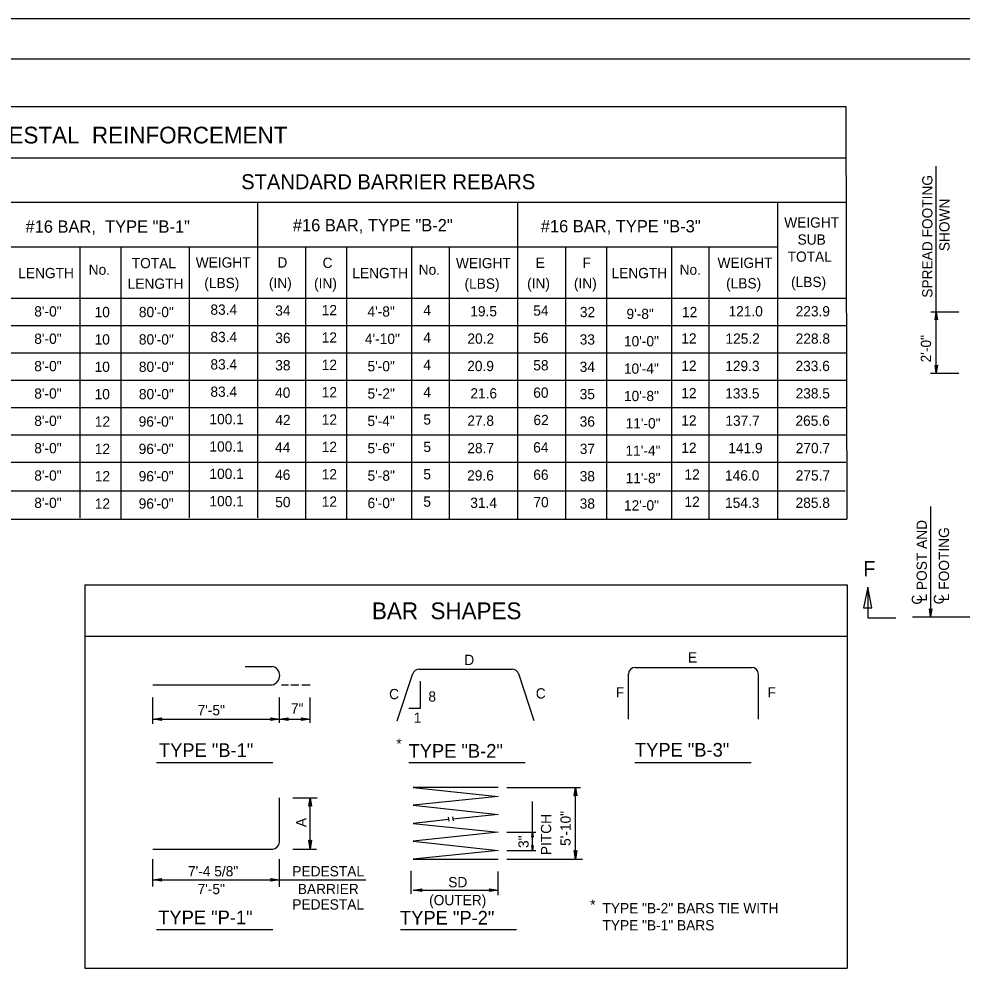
# Model space of a CAD drawing. Extents: x -3 to 26050223, y 0 to 12035012.
# Drawn here: x 21.31 to 44.29, y 20.2 to 43.33 of the extents above; entities that cross this region are included whole.
import ezdxf

# ---------------------------------------------------------------- set-up
doc = ezdxf.new("R2010")
doc.units = 0
for name, color, linetype in [('1', 7, 'Continuous'), ('2', 7, 'Continuous'), ('39', 7, 'Continuous')]:
    doc.layers.add(name, color=color, linetype=linetype)

msp = doc.modelspace()

# ---------------------------------------------------------------- linework, layer by layer
at = {"layer": '1'}
for p, q in [((68.892, 43.325), (0, 43.325)), ((68.183, 42.342), (3.6, 42.342))]:
    msp.add_line(p, q, dxfattribs=at)
at = {"layer": '2'}
for p, q in [((24.658, 25.208), (27.492, 25.208)), ((30.808, 25.208), (33.642, 25.208)), ((36.317, 25.208), (39.15, 25.208)), ((24.658, 21.142), (27.492, 21.142)), ((30.6, 21.142), (33.433, 21.142))]:
    msp.add_line(p, q, dxfattribs=at)
msp.add_arc((27.429, 27.325), 0.23, 281.6527, 78.3473, dxfattribs=at)
at = {"layer": '39'}
for p, q in [((4.871, 41.192), (41.454, 41.192)), ((41.454, 41.192), (41.482, 31.137)), ((4.871, 39.942), (41.454, 39.942)), ((43.658, 34.692), (43.658, 39.742)), ((9.121, 38.859), (41.454, 38.859)), ((27.121, 38.859), (27.121, 31.173)), ((33.454, 38.859), (33.454, 31.14)), ((39.788, 38.859), (39.788, 31.124)), ((9.121, 37.776), (39.788, 37.776)), ((22.788, 37.776), (22.788, 31.173)), ((23.788, 37.776), (23.788, 31.124)), ((25.454, 37.776), (25.454, 31.173)), ((28.288, 37.776), (28.288, 31.156)), ((29.288, 37.776), (29.288, 31.14)), ((30.871, 37.776), (30.871, 31.14)), ((31.788, 37.776), (31.788, 31.14)), ((34.621, 37.776), (34.621, 31.156)), ((35.621, 37.776), (35.621, 31.124)), ((37.204, 37.776), (37.204, 31.14)), ((38.121, 37.776), (38.121, 31.14)), ((4.871, 36.526), (41.454, 36.526)), ((43.525, 36.192), (44.208, 36.192)), ((4.871, 35.859), (41.454, 35.859)), ((4.871, 35.192), (41.454, 35.192)), ((43.517, 34.692), (44.208, 34.692)), ((4.871, 34.526), (41.454, 34.526)), ((4.871, 33.859), (41.454, 33.859)), ((4.871, 33.192), (41.454, 33.192)), ((4.871, 32.526), (41.454, 32.526)), ((4.859, 31.831), (41.442, 31.831)), ((43.522, 31.447), (43.522, 28.755)), ((4.898, 31.137), (41.482, 31.137)), ((22.908, 29.533), (22.908, 20.2)), ((22.908, 29.533), (41.492, 29.533)), ((41.492, 29.533), (41.492, 20.2)), ((41.988, 29.48), (41.888, 28.98)), ((41.988, 29.48), (41.888, 28.98)), ((42.088, 28.98), (41.988, 29.48)), ((42.088, 28.98), (41.988, 29.48)), ((41.988, 29.455), (41.988, 28.73)), ((41.888, 28.98), (42.088, 28.98)), ((41.888, 28.98), (42.088, 28.98)), ((41.988, 28.73), (42.672, 28.73)), ((43.08, 28.755), (46.405, 28.755)), ((22.908, 28.283), (41.492, 28.283)), ((26.817, 27.55), (27.475, 27.55)), ((36.325, 27.525), (39.158, 27.525)), ((30.525, 26.225), (30.9, 27.375)), ((31.058, 27.483), (33.325, 27.483)), ((33.858, 26.225), (33.483, 27.367)), ((36.158, 26.267), (36.158, 27.358)), ((39.325, 26.267), (39.325, 27.358)), ((24.567, 27.1), (27.475, 27.1)), ((27.7, 27.1), (27.875, 27.1)), ((27.933, 27.1), (28.125, 27.1)), ((28.2, 27.1), (28.4, 27.1)), ((31.092, 26.533), (31.092, 27.192)), ((24.567, 26.15), (24.567, 26.792)), ((27.65, 26.175), (27.65, 26.792)), ((28.4, 26.175), (28.4, 26.792)), ((30.808, 26.533), (31.092, 26.533)), ((24.567, 26.267), (27.65, 26.267)), ((27.65, 26.267), (28.4, 26.267)), ((32.983, 24.6), (30.908, 24.6)), ((30.908, 24.6), (32.983, 24.383)), ((32.983, 24.6), (30.908, 24.6)), ((30.908, 24.6), (32.983, 24.383)), ((33.192, 24.6), (34.992, 24.6)), ((34.867, 22.85), (34.867, 24.6)), ((27.65, 23.267), (27.65, 24.35)), ((27.975, 24.35), (28.575, 24.35)), ((28.4, 23.1), (28.4, 24.35)), ((32.983, 24.383), (30.908, 24.167)), ((32.983, 24.383), (30.908, 24.167)), ((30.908, 24.167), (32.983, 23.942)), ((30.908, 24.167), (32.983, 23.942)), ((33.817, 23.508), (33.817, 24.258)), ((31.767, 23.875), (31.783, 23.775)), ((31.867, 23.883), (31.883, 23.783)), ((32.983, 23.942), (31.875, 23.825)), ((32.983, 23.942), (31.875, 23.825)), ((31.775, 23.817), (30.908, 23.725)), ((31.783, 23.817), (30.908, 23.725)), ((30.908, 23.725), (32.983, 23.508)), ((30.908, 23.725), (32.983, 23.508)), ((32.983, 23.508), (30.908, 23.292)), ((32.983, 23.508), (30.908, 23.292)), ((33.192, 23.508), (33.9, 23.508)), ((33.817, 23.067), (33.817, 23.508)), ((30.908, 23.292), (32.983, 23.067)), ((30.908, 23.292), (32.983, 23.067)), ((24.567, 23.1), (27.483, 23.1)), ((27.975, 23.1), (28.558, 23.1)), ((32.983, 23.067), (30.908, 22.85)), ((32.983, 23.067), (30.908, 22.85)), ((33.192, 23.067), (33.9, 23.067)), ((24.567, 22.183), (24.567, 22.85)), ((27.65, 22.175), (27.65, 22.85)), ((30.908, 22.85), (32.983, 22.85)), ((30.908, 22.85), (32.983, 22.85)), ((33.192, 22.85), (35.042, 22.85)), ((30.864, 22.005), (30.864, 22.572)), ((32.983, 21.975), (32.983, 22.55)), ((24.567, 22.35), (29.758, 22.35)), ((30.908, 22.1), (32.983, 22.1)), ((22.908, 20.2), (41.492, 20.2))]:
    msp.add_line(p, q, dxfattribs=at)
for points in [[(43.658, 36.008), (43.633, 35.992), (43.658, 36.192), (43.692, 35.992)], [(43.658, 36.008), (43.633, 35.992), (43.658, 36.192), (43.692, 35.992)], [(43.658, 34.875), (43.692, 34.892), (43.658, 34.692), (43.633, 34.892)], [(43.658, 34.875), (43.692, 34.892), (43.658, 34.692), (43.633, 34.892)], [(43.522, 28.938), (43.555, 28.955), (43.522, 28.755), (43.497, 28.955)], [(24.758, 26.267), (24.783, 26.233), (24.567, 26.267), (24.783, 26.3)], [(27.458, 26.267), (27.442, 26.3), (27.65, 26.267), (27.442, 26.233)], [(27.842, 26.267), (27.867, 26.233), (27.65, 26.267), (27.867, 26.3)], [(28.208, 26.267), (28.192, 26.3), (28.4, 26.267), (28.192, 26.233)], [(34.867, 24.408), (34.833, 24.392), (34.867, 24.6), (34.9, 24.392)], [(28.4, 24.158), (28.367, 24.142), (28.4, 24.35), (28.433, 24.142)], [(33.817, 23.408), (33.8, 23.392), (33.817, 23.508), (33.833, 23.392)], [(28.4, 23.292), (28.433, 23.317), (28.4, 23.1), (28.367, 23.317)], [(33.817, 23.167), (33.833, 23.183), (33.817, 23.067), (33.8, 23.183)], [(34.867, 23.042), (34.9, 23.067), (34.867, 22.85), (34.833, 23.067)], [(24.758, 22.35), (24.783, 22.317), (24.567, 22.35), (24.783, 22.383)], [(27.458, 22.35), (27.442, 22.383), (27.65, 22.35), (27.442, 22.317)], [(31.1, 22.1), (31.125, 22.067), (30.908, 22.1), (31.125, 22.133)], [(32.792, 22.1), (32.775, 22.133), (32.983, 22.1), (32.775, 22.067)]]:
    msp.add_lwpolyline(points, close=True, dxfattribs=at)
for centre, start, end in [((36.325, 27.358), 90, 180), ((39.158, 27.358), 0, 90), ((31.06, 27.317), 90, 160.71), ((33.322, 27.317), 18.435, 90), ((27.483, 23.267), 270, 0)]:
    msp.add_arc(centre, 0.167, start, end, dxfattribs=at)

# ---------------------------------------------------------------- texts
at = {"layer": '1'}
msp.add_text('F', height=0.367, dxfattribs=at).set_placement((41.88, 29.747))
at = {"layer": '2'}
for s, height, p in [('STANDARD BARRIER REBARS', 0.36665, (26.721, 39.176)), ('#16 BAR,  TYPE "B-1"', 0.3, (21.463, 38.117)), ('#16 BAR, TYPE "B-2"', 0.3, (27.979, 38.151)), ('#16 BAR, TYPE "B-3"', 0.3, (34.021, 38.126)), ('WEIGHT', 0.25, (39.954, 38.242)), ('SUB', 0.25, (40.279, 37.826)), ('TOTAL', 0.25, (24.054, 37.251)), ('WEIGHT', 0.25, (25.613, 37.267)), ('D', 0.25, (27.604, 37.267)), ('C', 0.25, (28.704, 37.259)), ('WEIGHT', 0.25, (31.954, 37.251)), ('E', 0.25, (33.896, 37.259)), ('F', 0.25, (35.038, 37.259)), ('WEIGHT', 0.25, (38.329, 37.259)), ('TOTAL', 0.25, (40.038, 37.409)), ('LENGTH', 0.25, (21.288, 37.009)), ('No.', 0.25, (23.004, 37.092)), ('LENGTH', 0.25, (29.429, 37.009)), ('No.', 0.25, (31.046, 37.092)), ('LENGTH', 0.25, (35.746, 37.009)), ('No.', 0.25, (37.404, 37.092)), ('LENGTH', 0.25, (23.954, 36.751)), ('(LBS)', 0.25, (25.821, 36.767)), ('(IN)', 0.25, (27.396, 36.767)), ('(IN)', 0.25, (28.496, 36.759)), ('(LBS)', 0.25, (32.163, 36.751)), ('(IN)', 0.25, (33.688, 36.759)), ('(IN)', 0.25, (34.829, 36.759)), ('(LBS)', 0.25, (38.538, 36.759)), ('(LBS)', 0.25, (40.121, 36.792)), ('8\'-0"', 0.25, (21.678, 36.075)), ('10', 0.25, (23.148, 36.059)), ('80\'-0"', 0.25, (24.227, 36.059)), ('83.4', 0.25, (25.971, 36.118)), ('34', 0.25, (27.55, 36.095)), ('12', 0.25, (28.684, 36.106)), ('4\'-8"', 0.25, (29.798, 36.073)), ('4', 0.25, (31.16, 36.106)), ('19.5', 0.25, (32.303, 36.078)), ('54', 0.25, (33.839, 36.095)), ('32', 0.25, (34.974, 36.059)), ('12', 0.25, (37.463, 36.059)), ('121.0', 0.25, (38.597, 36.078)), ('223.9', 0.25, (40.232, 36.078)), ('9\'-8"', 0.25, (36.11, 36.014)), ('8\'-0"', 0.25, (21.678, 35.409)), ('10', 0.25, (23.148, 35.392)), ('80\'-0"', 0.25, (24.227, 35.392)), ('83.4', 0.25, (25.971, 35.451)), ('36', 0.25, (27.55, 35.428)), ('12', 0.25, (28.684, 35.44)), ('4\'-10"', 0.25, (29.736, 35.406)), ('4', 0.25, (31.16, 35.44)), ('20.2', 0.25, (32.234, 35.412)), ('56', 0.25, (33.839, 35.428)), ('33', 0.25, (34.97, 35.392)), ('12', 0.25, (37.446, 35.417)), ('125.2', 0.25, (38.523, 35.412)), ('228.8', 0.25, (40.234, 35.412)), ('10\'-0"', 0.25, (36.049, 35.348)), ('8\'-0"', 0.25, (21.678, 34.742)), ('10', 0.25, (23.148, 34.725)), ('80\'-0"', 0.25, (24.227, 34.725)), ('83.4', 0.25, (25.971, 34.784)), ('38', 0.25, (27.55, 34.762)), ('12', 0.25, (28.684, 34.773)), ('5\'-0"', 0.25, (29.799, 34.74)), ('4', 0.25, (31.16, 34.773)), ('20.9', 0.25, (32.229, 34.745)), ('58', 0.25, (33.839, 34.762)), ('34', 0.25, (34.969, 34.725)), ('10\'-4"', 0.25, (36.047, 34.681)), ('12', 0.25, (37.446, 34.751)), ('129.3', 0.25, (38.517, 34.745)), ('233.6', 0.25, (40.229, 34.745)), ('8\'-0"', 0.25, (21.678, 34.075)), ('10', 0.25, (23.148, 34.059)), ('80\'-0"', 0.25, (24.227, 34.059)), ('83.4', 0.25, (25.971, 34.118)), ('40', 0.25, (27.547, 34.095)), ('12', 0.25, (28.684, 34.106)), ('5\'-2"', 0.25, (29.8, 34.073)), ('4', 0.25, (31.16, 34.106)), ('21.6', 0.25, (32.306, 34.078)), ('60', 0.25, (33.838, 34.095)), ('35', 0.25, (34.97, 34.059)), ('10\'-8"', 0.25, (36.049, 34.014)), ('12', 0.25, (37.446, 34.084)), ('133.5', 0.25, (38.516, 34.078)), ('238.5', 0.25, (40.231, 34.078)), ('8\'-0"', 0.25, (21.678, 33.409)), ('12', 0.25, (23.153, 33.392)), ('96\'-0"', 0.25, (24.222, 33.392)), ('100.1', 0.25, (25.947, 33.451)), ('42', 0.25, (27.552, 33.428)), ('12', 0.25, (28.684, 33.44)), ('5\'-4"', 0.25, (29.797, 33.406)), ('5', 0.25, (31.16, 33.44)), ('27.8', 0.25, (32.231, 33.412)), ('62', 0.25, (33.843, 33.428)), ('36', 0.25, (34.97, 33.392)), ('11\'-0"', 0.25, (36.088, 33.348)), ('12', 0.25, (37.446, 33.417)), ('137.7', 0.25, (38.521, 33.412)), ('265.6', 0.25, (40.228, 33.412)), ('8\'-0"', 0.25, (21.678, 32.742)), ('12', 0.25, (23.153, 32.725)), ('96\'-0"', 0.25, (24.222, 32.725)), ('100.1', 0.25, (25.947, 32.784)), ('44', 0.25, (27.546, 32.762)), ('12', 0.25, (28.684, 32.773)), ('5\'-6"', 0.25, (29.798, 32.74)), ('5', 0.25, (31.16, 32.773)), ('28.7', 0.25, (32.232, 32.745)), ('64', 0.25, (33.837, 32.762)), ('37', 0.25, (34.972, 32.725)), ('11\'-4"', 0.25, (36.086, 32.681)), ('12', 0.25, (37.446, 32.751)), ('141.9', 0.25, (38.591, 32.745)), ('270.7', 0.25, (40.235, 32.745)), ('8\'-0"', 0.25, (21.678, 32.075)), ('12', 0.25, (23.153, 32.059)), ('96\'-0"', 0.25, (24.222, 32.059)), ('100.1', 0.25, (25.947, 32.118)), ('46', 0.25, (27.547, 32.095)), ('12', 0.25, (28.684, 32.106)), ('5\'-8"', 0.25, (29.8, 32.073)), ('5', 0.25, (31.16, 32.106)), ('29.6', 0.25, (32.227, 32.078)), ('66', 0.25, (33.838, 32.095)), ('38', 0.25, (34.97, 32.059)), ('11\'-8"', 0.25, (36.088, 32.014)), ('12', 0.25, (37.524, 32.103)), ('146.0', 0.25, (38.512, 32.078)), ('275.7', 0.25, (40.235, 32.078)), ('100.1', 0.25, (25.947, 31.451)), ('50', 0.25, (27.55, 31.428)), ('12', 0.25, (28.684, 31.44)), ('5', 0.25, (31.16, 31.44)), ('70', 0.25, (33.842, 31.428)), ('12', 0.25, (37.524, 31.437)), ('8\'-0"', 0.25, (21.678, 31.409)), ('12', 0.25, (23.153, 31.392)), ('96\'-0"', 0.25, (24.222, 31.392)), ('6\'-0"', 0.25, (29.799, 31.406)), ('31.4', 0.25, (32.303, 31.412)), ('38', 0.25, (34.97, 31.392)), ('12\'-0"', 0.25, (36.05, 31.348)), ('154.3', 0.25, (38.513, 31.412)), ('285.8', 0.25, (40.231, 31.412)), ('D', 0.25, (32.158, 27.583)), ('E', 0.25, (37.608, 27.642)), ('C', 0.25, (30.325, 26.75)), ('8', 0.25, (31.283, 26.692)), ('C', 0.25, (33.9, 26.767)), ('F', 0.25, (35.85, 26.792)), ('F', 0.25, (39.55, 26.792)), ('7\'-5"', 0.25, (25.658, 26.358)), ('7"', 0.25, (27.933, 26.4)), ('1', 0.25, (30.925, 26.175)), ('7\'-4 5/8"', 0.25, (25.425, 22.433)), ('PEDESTAL', 0.25, (27.967, 22.433)), ('7\'-5"', 0.25, (25.658, 22)), ('BARRIER', 0.25, (28.1, 22)), ('SD', 0.25, (31.767, 22.167)), ('(OUTER)', 0.25, (31.3, 21.73)), ('PEDESTAL', 0.25, (27.967, 21.625)), ('*', 0.25, (35.225, 21.617)), ('TYPE "B-2" BARS TIE WITH ', 0.25, (35.525, 21.533)), ('TYPE "B-1" BARS', 0.25, (35.525, 21.117))]:
    msp.add_text(s, height=height, dxfattribs=at).set_placement(p)
for s, p in [('SPREAD FOOTING ', (43.567, 36.533)), ('SHOWN', (43.983, 37.667)), ('2\'-0"', (43.533, 34.958)), ('L POST AND', (43.43, 29.13)), ('L FOOTING', (43.972, 29.138)), ('C', (43.313, 29.055)), ('C', (43.847, 29.063)), ('A', (28.308, 23.633)), ('PITCH', (34.275, 22.95)), ('5\'-10"', (34.75, 23.175)), ('3"', (33.725, 23.125))]:
    msp.add_text(s, height=0.25, rotation=90, dxfattribs=at).set_placement(p)
at = {"layer": '39'}
for s, height, p in [('BARRIER  PEDESTAL  REINFORCEMENT', 0.40835, (17.196, 40.292)), ('BAR  SHAPES', 0.40835, (29.908, 28.7)), ('TYPE "B-1"', 0.3334, (24.717, 25.342)), ('*', 0.25, (30.5, 25.542)), ('TYPE "B-3"', 0.3334, (36.317, 25.35)), ('TYPE "B-2"', 0.3334, (30.8, 25.325)), ('TYPE "P-1"', 0.3334, (24.7, 21.267)), ('TYPE "P-2"', 0.3334, (30.592, 21.258))]:
    msp.add_text(s, height=height, dxfattribs=at).set_placement(p)

doc.saveas('drawing.dxf')
